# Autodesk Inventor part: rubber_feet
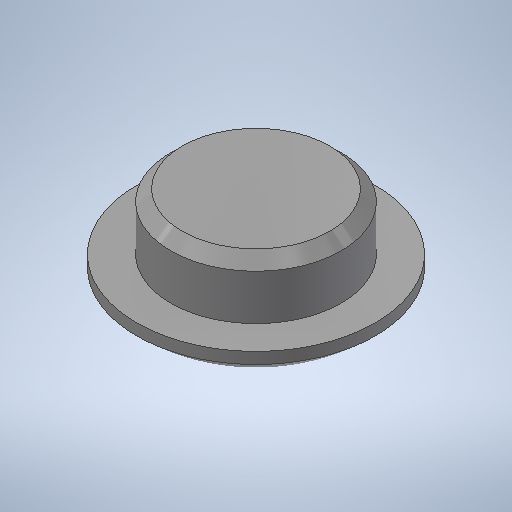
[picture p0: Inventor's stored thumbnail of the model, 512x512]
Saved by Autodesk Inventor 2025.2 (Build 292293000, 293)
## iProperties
Created: 2025-04
Part Number: rubber_feet
Material: 1.0037 S235JR
Document SubType Name: Modeling
Designer: BennF
Density: 7.85 g/cm^3
Appearance: Stahl
Author: BennF
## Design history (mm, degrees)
sketch "Sketch2"
  geometry: L1 (0, -5.144)-(0, 5.144); L2 (0, 5.144)-(-6.5, 5.144); L3 (-6.5, 5.144)-(-7.5, 4.144); L4 (-7.5, 4.144)-(-7.5, 0.144); L5 (-7.5, 0.144)-(-10.5, 0.144); L6 (-10.5, 0.144)-(-10.5, -0.856); A1 r 15 centre (0, 9.856) between (-10.5, -0.856) and (0, -5.144); 2 further points
  constraints: 12 end point, 2 perpendicular, 2 point on circle, 2 vertical, 1 centre point, 1 coincident, 1 horizontal, 1 midpoint, 1 point on line
  dimensions: "d0" = 15 diameter of L4 L1; "d1" = 135 deg angle of L2 L3; "d2" = 1 distance from line of L3.end L2; "d3" = 5 distance between parallel lines of L5 L2; "d4" = 3 distance of L4.end L5.end; "d5" = 15 radius of A1; "d7" = 1 distance of L5.end L6.end
revolve "Revolution1" sketch "Sketch2" stored, may be unused: angle "d6" = 90 deg
body "Solid1"
